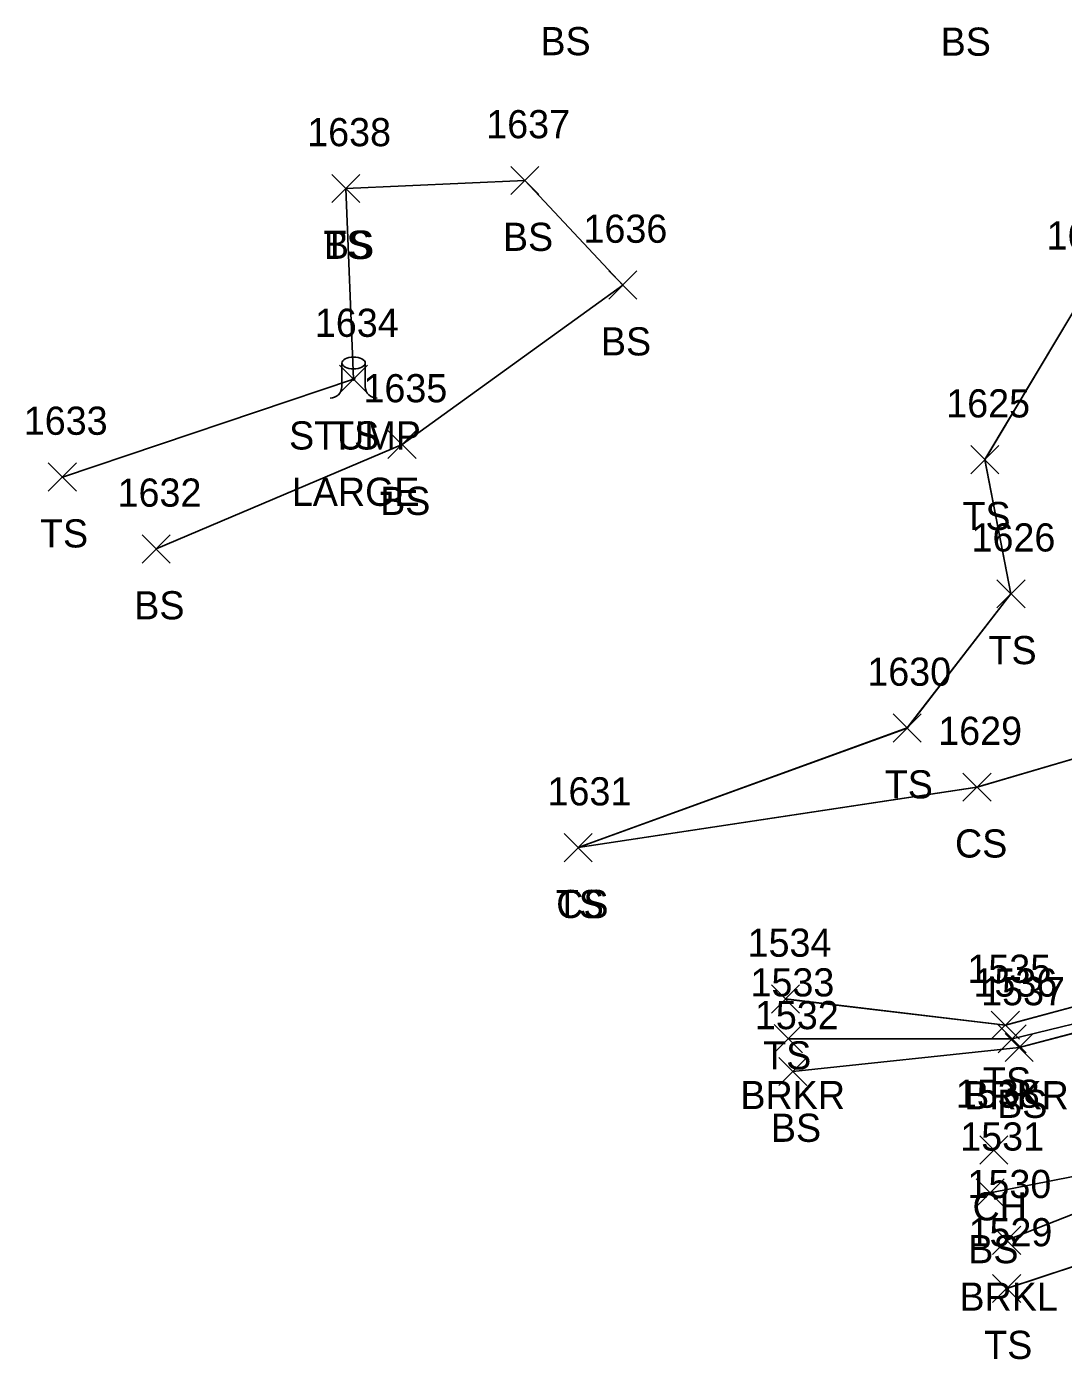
# Model space of a CAD drawing. Extents: x 1415642 to 1422021, y 544543 to 547232.
# Drawn here: x 1415969.5 to 1416043.1, y 546709.9 to 546804.5 of the extents above; entities that cross this region are included whole.
import ezdxf

# ---------------------------------------------------------------- set-up
doc = ezdxf.new("R2010")
doc.units = 0
for name, color, linetype in [('L_A', 7, 'Continuous'), ('L_C', 7, 'Continuous'), ('L_I', 7, 'Continuous'), ('L_TIC', 7, 'Continuous'), ('LAWE', 7, 'Continuous'), ('LELB', 7, 'Continuous'), ('LTS', 7, 'Continuous')]:
    doc.layers.add(name, color=color, linetype=linetype)

msp = doc.modelspace()

# ---------------------------------------------------------------- linework, layer by layer
at = {"layer": 'L_TIC'}
for points in [[(1416003.847, 546792.588), (1416005.847, 546794.588)], [(1416005.847, 546792.588), (1416003.847, 546794.588)], [(1415991.138, 546792.022), (1415993.138, 546794.022)], [(1415993.138, 546792.022), (1415991.138, 546794.022)], [(1415991.138, 546792.022), (1415993.138, 546794.022)], [(1415993.138, 546792.022), (1415991.138, 546794.022)], [(1416010.803, 546785.165), (1416012.803, 546787.165)], [(1416012.803, 546785.165), (1416010.803, 546787.165)], [(1415991.682, 546778.486), (1415993.682, 546780.486)], [(1415993.682, 546778.486), (1415991.682, 546780.486)], [(1415995.131, 546773.839), (1415997.131, 546775.839)], [(1415997.131, 546773.839), (1415995.131, 546775.839)], [(1416036.497, 546772.762), (1416038.497, 546774.762)], [(1416038.497, 546772.762), (1416036.497, 546774.762)], [(1415971.02, 546771.531), (1415973.02, 546773.531)], [(1415973.02, 546771.531), (1415971.02, 546773.531)], [(1415977.678, 546766.427), (1415979.678, 546768.427)], [(1415979.678, 546766.427), (1415977.678, 546768.427)], [(1416038.349, 546763.244), (1416040.349, 546765.244)], [(1416040.349, 546763.244), (1416038.349, 546765.244)], [(1416030.983, 546753.711), (1416032.983, 546755.711)], [(1416032.983, 546753.711), (1416030.983, 546755.711)], [(1416035.938, 546749.513), (1416037.938, 546751.513)], [(1416037.938, 546749.513), (1416035.938, 546751.513)], [(1416007.63, 546745.216), (1416009.63, 546747.216)], [(1416009.63, 546745.216), (1416007.63, 546747.216)], [(1416007.63, 546745.216), (1416009.63, 546747.216)], [(1416009.63, 546745.216), (1416007.63, 546747.216)], [(1416022.351, 546734.469), (1416024.351, 546736.469)], [(1416024.351, 546734.469), (1416022.351, 546736.469)], [(1416037.951, 546732.616), (1416039.951, 546734.616)], [(1416039.951, 546732.616), (1416037.951, 546734.616)], [(1416022.555, 546731.652), (1416024.555, 546733.652)], [(1416024.555, 546731.652), (1416022.555, 546733.652)], [(1416038.435, 546731.637), (1416040.435, 546733.637)], [(1416040.435, 546731.637), (1416038.435, 546733.637)], [(1416038.929, 546731.026), (1416040.929, 546733.026)], [(1416040.929, 546731.026), (1416038.929, 546733.026)], [(1416022.868, 546729.326), (1416024.868, 546731.326)], [(1416024.868, 546729.326), (1416022.868, 546731.326)], [(1416037.134, 546723.745), (1416039.134, 546725.745)], [(1416039.134, 546723.745), (1416037.134, 546725.745)], [(1416036.877, 546720.707), (1416038.877, 546722.707)], [(1416038.877, 546720.707), (1416036.877, 546722.707)], [(1416038.047, 546717.337), (1416040.047, 546719.337)], [(1416040.047, 546717.337), (1416038.047, 546719.337)], [(1416038.042, 546713.911), (1416040.042, 546715.911)], [(1416040.042, 546713.911), (1416038.042, 546715.911)]]:
    msp.add_lwpolyline(points, dxfattribs=at)
at = {"layer": 'LAWE'}
for points in [[(1416023.555, 546732.652), (1416039.435, 546732.637), (1416047.212, 546734.536), (1416056.672, 546740.419), (1416066.054, 546747.833), (1416069.262, 546752.019), (1416075.059, 546757.214), (1416081.661, 546764.919), (1416099.922, 546779.935), (1416116.018, 546793.533), (1416127.694, 546798.829)], [(1416023.56, 546732.655), (1416039.44, 546732.638), (1416047.218, 546734.533), (1416056.676, 546740.42), (1416066.062, 546747.829), (1416069.268, 546752.017), (1416075.064, 546757.213), (1416081.67, 546764.916), (1416099.925, 546779.935), (1416116.022, 546793.533), (1416127.702, 546798.828)], [(1416039.047, 546718.337), (1416052.784, 546723.735), (1416060.875, 546726.975), (1416074.377, 546737.683), (1416086.319, 546747.157), (1416093.425, 546752.758), (1416101.98, 546759.616), (1416111.397, 546767.511), (1416119.583, 546772.235), (1416127.403, 546776.082), (1416128.271, 546778.626), (1416129.002, 546780.644), (1416128.144, 546784.491), (1416130.448, 546789.914), (1416132.468, 546795.001), (1416130.863, 546797.224), (1416127.694, 546798.829)], [(1416039.053, 546718.334), (1416052.787, 546723.738), (1416060.879, 546726.977), (1416074.38, 546737.685), (1416086.328, 546747.153), (1416093.43, 546752.758), (1416101.985, 546759.615), (1416111.399, 546767.512), (1416119.591, 546772.233), (1416127.408, 546776.081), (1416128.28, 546778.625), (1416129.011, 546780.643), (1416128.148, 546784.491), (1416130.455, 546789.913), (1416132.475, 546795.001), (1416130.871, 546797.224), (1416127.702, 546798.828)]]:
    msp.add_lwpolyline(points, dxfattribs=at)
at = {"layer": 'LELB'}
for points in [[(1416145.272, 546792.192), (1416140.825, 546785.479), (1416135.571, 546781.553), (1416134.129, 546786.328), (1416133.182, 546791.545), (1416133.267, 546797.305), (1416128.672, 546801.948), (1416121.917, 546800.589), (1416115.746, 546796.749), (1416101.262, 546800.374), (1416080.073, 546796.226), (1416060.239, 546785.43), (1416047.261, 546780.092), (1416047.587, 546762.691), (1416049.577, 546754.218), (1416036.938, 546750.513), (1416008.63, 546746.216)], [(1416145.276, 546792.192), (1416140.832, 546785.478), (1416135.574, 546781.553), (1416134.133, 546786.328), (1416133.185, 546791.545), (1416133.273, 546797.304), (1416128.676, 546801.948), (1416121.918, 546800.589), (1416115.751, 546796.748), (1416101.27, 546800.373), (1416080.083, 546796.225), (1416060.246, 546785.429), (1416047.263, 546780.095), (1416047.594, 546762.689), (1416049.581, 546754.219), (1416036.944, 546750.511), (1416008.636, 546746.22)], [(1416101.262, 546800.374), (1416078.212, 546799.853), (1416057.31, 546790.638), (1416044.618, 546785.685), (1416037.497, 546773.762), (1416039.349, 546764.244), (1416031.983, 546754.711), (1416008.63, 546746.216)], [(1416101.27, 546800.373), (1416078.214, 546799.854), (1416057.312, 546790.64), (1416044.625, 546785.682), (1416037.501, 546773.766), (1416039.354, 546764.244), (1416031.987, 546754.714), (1416008.636, 546746.22)], [(1416023.351, 546735.469), (1416038.951, 546733.616), (1416046.683, 546735.69), (1416056.761, 546740.689), (1416065.626, 546748.326), (1416068.435, 546752.479), (1416073.833, 546759.454), (1416081.012, 546765.66), (1416098.794, 546781.576), (1416115.927, 546794.323)], [(1416023.356, 546735.47), (1416038.957, 546733.613), (1416046.689, 546735.687), (1416056.766, 546740.69), (1416065.629, 546748.329), (1416068.442, 546752.477), (1416073.835, 546759.456), (1416081.018, 546765.659), (1416098.798, 546781.576), (1416115.932, 546794.323)], [(1415978.678, 546767.427), (1415996.131, 546774.839), (1416011.803, 546786.165), (1416004.847, 546793.588), (1415992.138, 546793.022)], [(1415978.683, 546767.427), (1415996.138, 546774.841), (1416011.808, 546786.164), (1416004.851, 546793.586), (1415992.141, 546793.02)], [(1415972.02, 546772.531), (1415992.682, 546779.486), (1415992.138, 546793.022)], [(1415972.028, 546772.532), (1415992.689, 546779.488), (1415992.141, 546793.02)], [(1416023.868, 546730.326), (1416039.929, 546732.026), (1416046.981, 546733.886), (1416057.557, 546739.074), (1416066.711, 546747.347), (1416075.911, 546756.381), (1416082.063, 546763.674), (1416101.063, 546779.443), (1416117.288, 546793.166), (1416118.494, 546793.221)], [(1416023.873, 546730.325), (1416039.933, 546732.029), (1416046.987, 546733.882), (1416057.561, 546739.075), (1416066.718, 546747.345), (1416075.919, 546756.377), (1416082.067, 546763.675), (1416101.071, 546779.441), (1416117.289, 546793.167), (1416118.504, 546793.22)], [(1416037.877, 546721.707), (1416052.55, 546724.596), (1416060.793, 546727.919), (1416073.737, 546738.984), (1416085.425, 546747.563), (1416092.766, 546752.935), (1416101.789, 546760.083), (1416110.668, 546768.082), (1416119.329, 546772.875), (1416125.133, 546776.758), (1416125.641, 546785.647), (1416122.227, 546788.667), (1416118.494, 546793.221)], [(1416037.883, 546721.703), (1416052.556, 546724.595), (1416060.799, 546727.917), (1416073.743, 546738.982), (1416085.432, 546747.561), (1416092.771, 546752.934), (1416101.793, 546760.083), (1416110.675, 546768.081), (1416119.331, 546772.875), (1416125.136, 546776.759), (1416125.643, 546785.648), (1416122.228, 546788.667), (1416118.504, 546793.22)], [(1416057.108, 546720.869), (1416039.042, 546714.911)], [(1416057.114, 546720.867), (1416039.048, 546714.91)]]:
    msp.add_lwpolyline(points, dxfattribs=at)
at = {"layer": 'LTS'}
for p, q in [((1415991.853, 546780.626), (1415991.853, 546778.96)), ((1415993.52, 546780.46), (1415993.52, 546780.626)), ((1415993.52, 546780.626), (1415993.52, 546778.96)), ((1415992.686, 546779.484), (1415992.686, 546779.484)), ((1415992.686, 546779.484), (1415992.686, 546779.484)), ((1415992.686, 546779.46), (1415992.686, 546779.46))]:
    msp.add_line(p, q, dxfattribs=at)
msp.add_circle((1415992.686, 546779.484), 0.0833, dxfattribs=at)
for centre, start, end in [((1415991.02, 546778.96), 270, 360), ((1415994.353, 546778.96), 180, 270)]:
    msp.add_arc(centre, 0.833, start, end, dxfattribs=at)
msp.add_ellipse((1415992.686, 546780.626), major_axis=(-0.833, 0), ratio=0.5, dxfattribs=at)

# ---------------------------------------------------------------- texts
at = {"layer": 'L_A'}
for s, p in [('BS', (1416005.951, 546802.482)), ('BS', (1416034.361, 546802.447)), ('BS', (1416003.288, 546788.588)), ('TS', (1415990.547, 546788.022)), ('BS', (1415990.579, 546788.022)), ('BS', (1416010.244, 546781.165)), ('STUMP', (1415988.107, 546774.486)), ('TS', (1415991.091, 546774.486)), ('BS', (1415994.572, 546769.839)), ('TS', (1416035.907, 546768.762)), ('TS', (1415970.43, 546767.531)), ('BS', (1415977.119, 546762.427)), ('TS', (1416037.758, 546759.244)), ('TS', (1416030.392, 546749.711)), ('CS', (1416035.379, 546745.513)), ('TS', (1416007.04, 546741.216)), ('CS', (1416007.071, 546741.216)), ('TS', (1416021.76, 546730.469)), ('TS', (1416037.361, 546728.616)), ('BRKR', (1416020.145, 546727.652)), ('BRKR', (1416036.026, 546727.637)), ('BS', (1416038.37, 546727.026)), ('BS', (1416022.309, 546725.326)), ('CH', (1416036.622, 546719.745)), ('BS', (1416036.318, 546716.707)), ('BRKL', (1416035.693, 546713.337)), ('TS', (1416037.451, 546709.911))]:
    msp.add_text(s, height=2, dxfattribs=at).set_placement(p)
at = {"layer": 'L_C'}
msp.add_text('LARGE', height=2, dxfattribs=at).set_placement((1415988.304, 546770.486))
at = {"layer": 'L_I'}
for s, p in [('1638', (1415989.398, 546796.022)), ('1638', (1415989.398, 546796.022)), ('1637', (1416002.107, 546796.588)), ('1636', (1416009.008, 546789.165)), ('1623', (1416041.878, 546788.685)), ('1634', (1415989.942, 546782.486)), ('1634', (1415989.942, 546782.486)), ('1635', (1415993.391, 546777.839)), ('1625', (1416034.757, 546776.762)), ('1633', (1415969.28, 546775.531)), ('1632', (1415975.938, 546770.427)), ('1626', (1416036.553, 546767.244)), ('1630', (1416029.156, 546757.711)), ('1629', (1416034.19, 546753.513)), ('1631', (1416006.457, 546749.216)), ('1631', (1416006.457, 546749.216)), ('1534', (1416020.658, 546738.469)), ('1535', (1416036.258, 546736.616)), ('1533', (1416020.862, 546735.652)), ('1536', (1416036.687, 546735.637)), ('1537', (1416037.236, 546735.026)), ('1532', (1416021.175, 546733.326)), ('1538', (1416035.441, 546727.745)), ('1531', (1416035.751, 546724.707)), ('1530', (1416036.267, 546721.337)), ('1529', (1416036.341, 546717.911))]:
    msp.add_text(s, height=2, dxfattribs=at).set_placement(p)

doc.saveas('drawing.dxf')
